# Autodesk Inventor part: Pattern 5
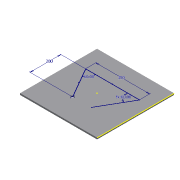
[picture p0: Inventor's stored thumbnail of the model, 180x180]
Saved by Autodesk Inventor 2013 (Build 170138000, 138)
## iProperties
Created: 2012-08
Part Number: Pattern 5
Material: Generic
Document SubType Name: Modeling
Designer: ANGEL
Mass: 2484.29 g
Surface Area: 5200 cm^2
Volume: 2484.29 cm^3
Density: 1 g/cm^3
Author: ANGEL
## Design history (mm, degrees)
sketch "Sketch1"
  geometry: L1 (-250, 250)-(250, 250); L2 (250, 250)-(250, -250); L3 (250, -250)-(-250, -250); L4 (-250, -250)-(-250, 250); 3 further points
  constraints: 8 end point, 2 midpoint, 2 parallel, 1 horizontal, 1 horizontal alignment, 1 perpendicular, 1 vertical alignment
  dimensions: "d0" = 500 distance of L2.end L3.end; "d1" = 500 distance of L1.end L2.end
extrude "Extrusion1" new body sketch "Sketch1" stored distance "d2" = 10; taper "d3" = 0 deg
sketch "Sketch2"
  geometry: L1 (250, -250)-(250, 250) reference; L2 (-59.53, -100)-(-175, 100); L3 (-175, 100)-(175, 100); L4 (175, 100)-(59.53, -100); 4 further points
  constraints: 6 end point, 2 horizontal alignment, 2 midpoint, 1 coincident, 1 perpendicular, 1 vertical alignment
  dimensions: "d4" = 200 vertical distance of L2.start L2.end; "d6" = 350 distance of L2.end L3.end; "d7" = 60 deg angle of L3 L2; "d8" = 60 deg angle of L3 L4 (= d7)
hole "Hole1" sketch "Sketch2" diameter "d9" = 20; stored, may be unused: countersink angle "d13" = 90 deg, drill point angle "d15" = 118 deg; dims "d10" = 6, "d11" = 4, "d12" = 2, "d14" = 8
body "Solid1"
